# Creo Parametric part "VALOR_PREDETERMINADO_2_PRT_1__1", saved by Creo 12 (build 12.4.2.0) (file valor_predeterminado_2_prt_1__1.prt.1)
Units: Custom; MM, KILOGRAM, SECS

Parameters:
  PTC_WM_ITERATION = "0"
  PTC_WM_VERSION = "-.0"
  PTC_WM_LIFECYCLE_STATE = "In Work"
  PTC_WM_LIFECYCLE = "MO_CADDocument"
  PTC_WM_CREATED_BY = "Maximilian Roepper (Z0017RMS: MO)"
  PTC_WM_CREATED_ON = "18-Sep-26 11:36:42 AM"
  PTC_WM_MODIFIED_BY = "Maximilian Roepper (Z0017RMS: MO)"
  PTC_WM_MODIFIED_ON = "18-Sep-26 11:36:46 AM"
  PDMLINKNUMBER = "PDM000071455065"
  PTC_WM_NAME = "valor_predeterminado_2_prt_1__1.prt"
  PTC_WM_NUMBER = "PDM000071455065"

Other parameters: WEIGHT, WEIGHT_FACTOR, WEIGHT_ADD, _MASS_TEMP, _DIFF_TEMP, MC_ERRORS, SUPPLIER

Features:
  1. coordinate system
  2. datum plane "PRT_YZ"
  3. datum plane "PRT_XY"
  4. datum plane "PRT_XZ"
  5. coordinate system
  6. datum axis
  7. datum axis
  8. datum axis
  9. coordinate system
  10. imported feature
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
Other named items: PRT, SIEMENS_MO, DRW_VIEW_ORG, PRT_X, PRT_Y, PRT_Z, CS0, ROUGH_GROB

Layers: 00_STD_CSYS-KSYS, 01_STD_PLANES-EBENEN, 02_STD_AXES-ACHSEN, 03_STD_CSYS-KSYS, 24_IMPORT_FEAT-IMPORT_KE

Surfaces: 39 plane, 20 cylinder, 20 tabulated cylinder, 8 torus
